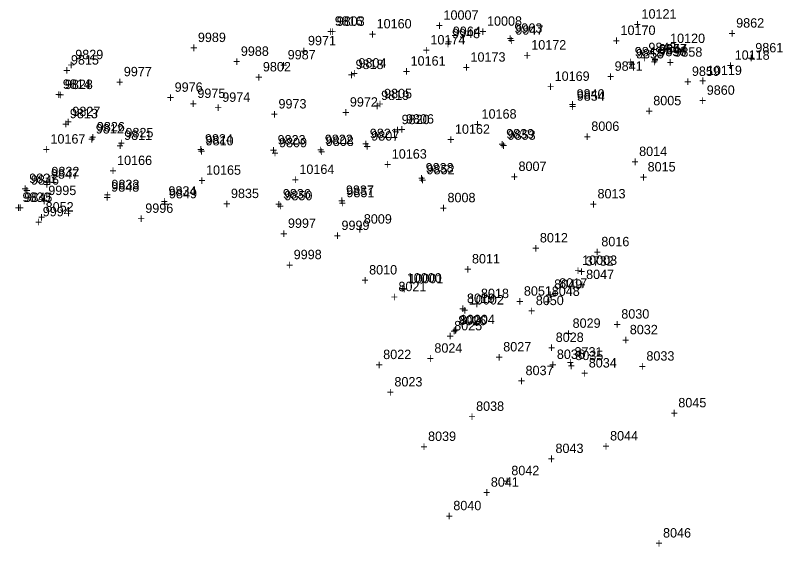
# Model space of a CAD drawing. Extents: x 1136220 to 1137808, y 528804 to 531215.
# Drawn here: x 1137116.2 to 1137320.1, y 528803.7 to 528944.9 of the extents above; entities that cross this region are included whole.
import ezdxf

# ---------------------------------------------------------------- set-up
doc = ezdxf.new("R2010")
doc.units = 0
for name, color, linetype in [('S_Annotation_Label', 7, 'Continuous'), ('S_Curb_Type_3', 7, 'Continuous'), ('S_Drainage_Culvert_Top', 7, 'Continuous'), ('S_Drainage_Invert', 7, 'Continuous'), ('S_Fencing_ChainLink', 7, 'Continuous'), ('S_Ground_Elevation', 7, 'Continuous'), ('S_Ground_LevelString', 7, 'Continuous'), ('S_Ground_SpotElevation', 7, 'Continuous'), ('S_Property_ConcPad', 7, 'Continuous'), ('S_Property_IronPipeFound', 7, 'Continuous'), ('S_Roadway_Edge_Pavement', 7, 'Continuous'), ('S_Roadway_Monument', 7, 'Continuous'), ('S_Trees_Bush_Line', 7, 'Continuous'), ('S_Trees_Decid_NonPay', 7, 'Continuous'), ('S_Trees_Decid_Pay', 7, 'Continuous')]:
    doc.layers.add(name, color=color, linetype=linetype)

msp = doc.modelspace()

# ---------------------------------------------------------------- texts
at = {"layer": 'S_Annotation_Label'}
for s, p in [('9802', (1137181.99, 528930.04)), ('+', (1137179.93, 528927.29))]:
    msp.add_text(s, height=2.5, dxfattribs=at).set_placement(p)
at = {"layer": 'S_Curb_Type_3'}
for s, p in [('9816', (1137201.09, 528942.19)), ('+', (1137199.03, 528939.44)), ('9964', (1137232.45, 528939.46)), ('9963', (1137248.8, 528940.32)), ('+', (1137246.74, 528937.57)), ('+', (1137230.39, 528936.71)), ('9829', (1137132.14, 528933.29)), ('9855', (1137281.12, 528933.5)), ('9856', (1137287.09, 528934.09)), ('9818', (1137206.61, 528930.66)), ('+', (1137285.03, 528931.34)), ('+', (1137130.08, 528930.54)), ('+', (1137279.06, 528930.75)), ('+', (1137204.55, 528927.91)), ('9828', (1137129.37, 528925.35)), ('9819', (1137213.41, 528922.43)), ('+', (1137127.3, 528922.6)), ('9854', (1137265.39, 528922.25)), ('+', (1137211.35, 528919.68)), ('+', (1137263.33, 528919.5)), ('9827', (1137131.37, 528918.16)), ('+', (1137129.31, 528915.41)), ('9820', (1137218.85, 528916.02)), ('9826', (1137137.87, 528914.09)), ('9825', (1137145.47, 528912.52)), ('9821', (1137210.4, 528912.31)), ('+', (1137216.79, 528913.27)), ('+', (1137135.81, 528911.34)), ('9824', (1137166.6, 528910.85)), ('9823', (1137185.91, 528910.61)), ('9822', (1137198.44, 528910.73)), ('9853', (1137247.01, 528911.87)), ('+', (1137143.41, 528909.77)), ('+', (1137208.34, 528909.56)), ('+', (1137244.95, 528909.12)), ('+', (1137164.54, 528908.1)), ('+', (1137183.85, 528907.86)), ('+', (1137196.38, 528907.98)), ('9852', (1137225.48, 528902.69)), ('9846', (1137120.37, 528899.94)), ('9847', (1137125.67, 528901.53)), ('+', (1137123.61, 528898.78)), ('9848', (1137141.7, 528898.08)), ('+', (1137223.42, 528899.94)), ('+', (1137118.31, 528897.19)), ('9849', (1137157.04, 528896.31)), ('9850', (1137187.7, 528895.78)), ('9851', (1137204.19, 528896.6)), ('9845', (1137118.61, 528895.34)), ('+', (1137139.63, 528895.33)), ('+', (1137116.55, 528892.59)), ('+', (1137154.97, 528893.56)), ('+', (1137185.64, 528893.03)), ('+', (1137202.13, 528893.85))]:
    msp.add_text(s, height=2.5, dxfattribs=at).set_placement(p)
at = {"layer": 'S_Drainage_Culvert_Top'}
for s, p in [('3732', (1137267.76, 528878.39)), ('+', (1137265.7, 528875.64))]:
    msp.add_text(s, height=2.5, dxfattribs=at).set_placement(p)
at = {"layer": 'S_Drainage_Invert'}
for s, p in [('3731', (1137264.78, 528854.24)), ('+', (1137262.71, 528851.49))]:
    msp.add_text(s, height=2.5, dxfattribs=at).set_placement(p)
at = {"layer": 'S_Fencing_ChainLink'}
for s, p in [('8052', (1137124.27, 528892.8)), ('+', (1137122.21, 528890.05)), ('8019', (1137236.21, 528868.49)), ('+', (1137234.15, 528865.74))]:
    msp.add_text(s, height=2.5, dxfattribs=at).set_placement(p)
at = {"layer": 'S_Ground_Elevation'}
for s, p in [('10007', (1137229.98, 528943.77)), ('10008', (1137241.54, 528942.18)), ('+', (1137227.92, 528941.02)), ('+', (1137239.48, 528939.43)), ('9989', (1137164.72, 528937.85)), ('9971', (1137193.97, 528936.99)), ('+', (1137162.66, 528935.1)), ('9988', (1137176.13, 528934.18)), ('9987', (1137188.58, 528933.24)), ('+', (1137191.91, 528934.24)), ('+', (1137174.07, 528931.43)), ('9977', (1137145.04, 528928.75)), ('+', (1137186.52, 528930.49)), ('+', (1137142.98, 528926)), ('9976', (1137158.55, 528924.62)), ('9975', (1137164.58, 528922.98)), ('+', (1137156.48, 528921.87)), ('9974', (1137171.19, 528921.95)), ('9972', (1137205.1, 528920.67)), ('8005', (1137285.71, 528921.04)), ('+', (1137162.52, 528920.23)), ('+', (1137169.13, 528919.2)), ('9973', (1137186.13, 528920.19)), ('+', (1137184.07, 528917.44)), ('+', (1137203.04, 528917.92)), ('+', (1137283.65, 528918.29)), ('8006', (1137269.25, 528914.23)), ('+', (1137267.19, 528911.48)), ('8014', (1137281.96, 528907.55)), ('+', (1137279.9, 528904.8)), ('8007', (1137249.91, 528903.58)), ('8015', (1137284.21, 528903.45)), ('+', (1137247.85, 528900.83)), ('+', (1137282.15, 528900.7)), ('9995', (1137124.97, 528897.17)), ('8013', (1137270.9, 528896.29)), ('+', (1137122.91, 528894.42)), ('8008', (1137231.04, 528895.26)), ('9996', (1137150.74, 528892.44)), ('+', (1137228.98, 528892.51)), ('+', (1137268.84, 528893.54)), ('+', (1137148.68, 528889.69)), ('9997', (1137188.65, 528888.44)), ('8009', (1137208.81, 528889.58)), ('+', (1137206.75, 528886.83)), ('+', (1137186.58, 528885.69)), ('8012', (1137255.59, 528884.58)), ('8016', (1137271.91, 528883.56)), ('+', (1137253.53, 528881.83)), ('+', (1137269.85, 528880.81)), ('8011', (1137237.54, 528879)), ('8010', (1137210.22, 528876.06)), ('+', (1137235.48, 528876.25)), ('+', (1137208.16, 528873.31)), ('8021', (1137218, 528871.62)), ('8017', (1137260.72, 528872.56)), ('8018', (1137239.93, 528869.79)), ('+', (1137258.66, 528869.81)), ('+', (1137215.94, 528868.87)), ('+', (1137237.87, 528867.04)), ('8030', (1137277.22, 528864.33)), ('8025', (1137232.82, 528861.21)), ('8026', (1137233.9, 528862.57)), ('8029', (1137264.28, 528861.88)), ('+', (1137275.16, 528861.58)), ('+', (1137231.84, 528859.82)), ('+', (1137230.76, 528858.46)), ('8028', (1137259.79, 528858.13)), ('+', (1137262.21, 528859.13)), ('8024', (1137227.56, 528855.27)), ('8027', (1137245.85, 528855.61)), ('8022', (1137213.96, 528853.57)), ('+', (1137257.72, 528855.38)), ('8036', (1137260.1, 528853.61)), ('8035', (1137265.01, 528853.3)), ('8033', (1137283.89, 528853.16)), ('+', (1137225.5, 528852.52)), ('+', (1137243.79, 528852.86)), ('8034', (1137268.58, 528851.33)), ('+', (1137211.9, 528850.82)), ('8037', (1137251.78, 528849.3)), ('+', (1137258.04, 528850.86)), ('+', (1137262.95, 528850.55)), ('+', (1137281.83, 528850.41)), ('+', (1137266.52, 528848.58)), ('8023', (1137216.94, 528846.3)), ('+', (1137249.72, 528846.55)), ('+', (1137214.88, 528843.55)), ('8045', (1137292.37, 528840.74)), ('8038', (1137238.64, 528839.81)), ('+', (1137290.31, 528837.99)), ('+', (1137236.58, 528837.06)), ('8039', (1137225.88, 528831.81)), ('8044', (1137274.24, 528831.94)), ('+', (1137223.82, 528829.06)), ('8043', (1137259.73, 528828.6)), ('+', (1137272.18, 528829.19)), ('+', (1137257.67, 528825.85)), ('8042', (1137248, 528822.7)), ('8041', (1137242.56, 528819.65)), ('+', (1137245.94, 528819.95)), ('+', (1137240.5, 528816.9)), ('8040', (1137232.59, 528813.39)), ('+', (1137230.53, 528810.64))]:
    msp.add_text(s, height=2.5, dxfattribs=at).set_placement(p)
at = {"layer": 'S_Ground_LevelString'}
for s, p in [('10121', (1137282.59, 528944.08)), ('10160', (1137212.21, 528941.48)), ('+', (1137280.53, 528941.33)), ('10170', (1137277.01, 528939.75)), ('+', (1137210.15, 528938.73)), ('10174', (1137226.51, 528937.2)), ('+', (1137274.95, 528937)), ('10120', (1137290.18, 528937.59)), ('10172', (1137253.29, 528935.86)), ('+', (1137224.45, 528934.45)), ('10173', (1137237.15, 528932.63)), ('+', (1137251.22, 528933.11)), ('+', (1137288.12, 528934.84)), ('10118', (1137307.34, 528933.14)), ('10161', (1137221.23, 528931.59)), ('+', (1137219.17, 528928.84)), ('+', (1137235.09, 528929.88)), ('10119', (1137299.96, 528929.08)), ('+', (1137305.27, 528930.39)), ('10169', (1137259.51, 528927.53)), ('+', (1137257.45, 528924.78)), ('+', (1137297.89, 528926.33)), ('10168', (1137240.09, 528917.49)), ('+', (1137238.03, 528914.74)), ('10162', (1137233.01, 528913.45)), ('10167', (1137125.55, 528910.86)), ('+', (1137230.95, 528910.7)), ('+', (1137123.49, 528908.11)), ('10163', (1137216.24, 528906.86)), ('10166', (1137143.26, 528905.16)), ('+', (1137141.2, 528902.41)), ('10165', (1137166.88, 528902.57)), ('10164', (1137191.69, 528902.79)), ('+', (1137214.18, 528904.11)), ('+', (1137164.82, 528899.82)), ('+', (1137189.63, 528900.05))]:
    msp.add_text(s, height=2.5, dxfattribs=at).set_placement(p)
at = {"layer": 'S_Ground_SpotElevation'}
for s, p in [('8032', (1137279.48, 528860.17)), ('+', (1137277.42, 528857.42)), ('8046', (1137288.31, 528806.14)), ('+', (1137286.25, 528803.39))]:
    msp.add_text(s, height=2.5, dxfattribs=at).set_placement(p)
at = {"layer": 'S_Property_ConcPad'}
for s, p in [('9862', (1137307.74, 528941.68)), ('+', (1137305.68, 528938.93)), ('9857', (1137287.24, 528934.83)), ('9861', (1137312.82, 528935.11)), ('9858', (1137291.32, 528933.96)), ('+', (1137285.18, 528932.08)), ('+', (1137289.25, 528931.21)), ('+', (1137310.75, 528932.36)), ('9859', (1137295.98, 528928.84)), ('+', (1137293.92, 528926.09)), ('9860', (1137299.92, 528923.83)), ('+', (1137297.86, 528921.08))]:
    msp.add_text(s, height=2.5, dxfattribs=at).set_placement(p)
at = {"layer": 'S_Property_IronPipeFound'}
for s, p in [('8020', (1137234.28, 528862.78)), ('10004', (1137234.32, 528862.86)), ('+', (1137232.21, 528860.03)), ('+', (1137232.26, 528860.11))]:
    msp.add_text(s, height=2.5, dxfattribs=at).set_placement(p)
at = {"layer": 'S_Roadway_Edge_Pavement'}
for s, p in [('9803', (1137201.61, 528942.15)), ('+', (1137199.55, 528939.4)), ('9948', (1137232.26, 528938.88)), ('9947', (1137249.09, 528939.8)), ('+', (1137247.03, 528937.05)), ('+', (1137230.2, 528936.13)), ('9843', (1137284.42, 528935.17)), ('9844', (1137287.27, 528934.58)), ('9842', (1137280.79, 528934.04)), ('9815', (1137130.99, 528931.86)), ('9804', (1137207.38, 528931.06)), ('+', (1137278.73, 528931.29)), ('+', (1137282.36, 528932.42)), ('+', (1137285.21, 528931.83)), ('+', (1137128.93, 528929.11)), ('9841', (1137275.45, 528930.21)), ('+', (1137205.32, 528928.31)), ('+', (1137273.39, 528927.46)), ('9814', (1137128.83, 528925.42)), ('9805', (1137214.19, 528922.92)), ('9840', (1137265.34, 528922.81)), ('+', (1137126.77, 528922.67)), ('+', (1137212.13, 528920.17)), ('+', (1137263.28, 528920.06)), ('9813', (1137130.71, 528917.59)), ('9806', (1137220, 528916.16)), ('+', (1137128.65, 528914.84)), ('9812', (1137137.6, 528913.54)), ('+', (1137217.93, 528913.41)), ('9839', (1137246.64, 528912.23)), ('+', (1137135.54, 528910.79)), ('9811', (1137145.14, 528911.83)), ('9810', (1137166.77, 528910.38)), ('9808', (1137198.7, 528910.22)), ('9807', (1137210.78, 528911.65)), ('+', (1137143.08, 528909.08)), ('9809', (1137186.29, 528909.88)), ('+', (1137208.72, 528908.9)), ('+', (1137244.58, 528909.48)), ('+', (1137164.71, 528907.63)), ('+', (1137184.23, 528907.13)), ('+', (1137196.63, 528907.47)), ('9832', (1137125.8, 528902.17)), ('9838', (1137225.24, 528903.17)), ('9831', (1137119.91, 528900.38)), ('+', (1137223.18, 528900.42)), ('+', (1137123.74, 528899.42)), ('9833', (1137141.75, 528898.74)), ('+', (1137117.85, 528897.63)), ('9834', (1137156.9, 528897.01)), ('9835', (1137173.51, 528896.37)), ('9836', (1137187.29, 528896.27)), ('9837', (1137204.05, 528897.22)), ('9830', (1137118.12, 528895.36)), ('+', (1137139.69, 528895.99)), ('+', (1137154.84, 528894.26)), ('+', (1137201.99, 528894.47)), ('+', (1137116.06, 528892.61)), ('+', (1137171.45, 528893.62)), ('+', (1137185.23, 528893.52))]:
    msp.add_text(s, height=2.5, dxfattribs=at).set_placement(p)
at = {"layer": 'S_Roadway_Monument'}
for s, p in [('9994', (1137123.5, 528891.53)), ('+', (1137121.43, 528888.78))]:
    msp.add_text(s, height=2.5, dxfattribs=at).set_placement(p)
at = {"layer": 'S_Trees_Bush_Line'}
for s, p in [('9999', (1137202.87, 528887.88)), ('+', (1137200.81, 528885.13)), ('9998', (1137190.18, 528880.12)), ('10003', (1137266.81, 528878.62)), ('+', (1137188.12, 528877.37)), ('+', (1137264.75, 528875.87)), ('10000', (1137220.21, 528873.91)), ('10001', (1137220.62, 528873.73)), ('+', (1137218.15, 528871.16)), ('+', (1137218.56, 528870.98)), ('10002', (1137236.71, 528868.08)), ('+', (1137234.65, 528865.33))]:
    msp.add_text(s, height=2.5, dxfattribs=at).set_placement(p)
at = {"layer": 'S_Trees_Decid_NonPay'}
for s, p in [('8049', (1137259.38, 528872.24)), ('8050', (1137254.5, 528867.92)), ('+', (1137257.32, 528869.49)), ('+', (1137252.44, 528865.17))]:
    msp.add_text(s, height=2.5, dxfattribs=at).set_placement(p)
at = {"layer": 'S_Trees_Decid_Pay'}
for s, p in [('8047', (1137267.87, 528874.85)), ('+', (1137265.81, 528872.1)), ('8051', (1137251.34, 528870.43)), ('8048', (1137258.75, 528870.37)), ('+', (1137249.28, 528867.68)), ('+', (1137256.69, 528867.62))]:
    msp.add_text(s, height=2.5, dxfattribs=at).set_placement(p)

doc.saveas('drawing.dxf')
